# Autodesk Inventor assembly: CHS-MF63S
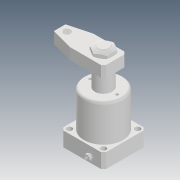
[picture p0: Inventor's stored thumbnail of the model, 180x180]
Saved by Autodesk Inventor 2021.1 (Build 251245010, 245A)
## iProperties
Created: 2019-05
Part Number: CHS-MF63S
Description: STEP AP203
Document SubType Name: Assembly
Designer: user
Title: chs-mf63s_asm.STEP
Revision Number: ÈÎºÎ
Sending System: SolidWorks 2017
Preprocessor: SwSTEP 2.0
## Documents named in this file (9)
- D:\Vault_2016\Projekty\Clamptek\Hydraulic\CHS\CHS-63\Inventor\CHS-MF63S\CHS-MF63S.iam
- D:\Vault_2016\Projekty\Clamptek\Hydraulic\CHS\CHS-63\Inventor\CHS-MF63S\CHS-MF63-03_1.ipt
- D:\Vault_2016\Projekty\Clamptek\Hydraulic\CHS\CHS-63\Inventor\CHS-MF63S\CHS-63S-02_3_1.ipt
- D:\Vault_2016\Projekty\Clamptek\Hydraulic\CHS\CHS-63\Inventor\CHS-MF63S\CHS-63S-01_4.ipt
- D:\Vault_2016\Projekty\Clamptek\Hydraulic\CHS\CHS-63\Inventor\CHS-MF63S\CHS-TXF-01_2.ipt
- D:\Vault_2016\Projekty\Clamptek\Hydraulic\CHS\CHS-63\Inventor\CHS-MF63S\CHS-MF40-TXF-03_2.ipt
- D:\Vault_2016\Projekty\Clamptek\Hydraulic\CHS\CHS-63\Inventor\CHS-MF63S\CHS-MF40-TXF-02_2.ipt
- D:\Vault_2016\Projekty\Clamptek\Hydraulic\CHS\CHS-63\Inventor\CHS-MF63S\M6_2.ipt
- D:\Vault_2016\Projekty\Clamptek\Hydraulic\CHS\CHS-63\Inventor\CHS-MF63S\M24_4.ipt
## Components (8 placed, 8 different names)
1. CHS-MF63-03_1_1
2. CHS-63S-02_3_1_2
3. CHS-63S-01_4_3
4. CHS-TXF-01_2_4
5. CHS-MF40-TXF-03_2_5
6. CHS-MF40-TXF-02_2_6
7. M6_2_7
8. M24_4_8
